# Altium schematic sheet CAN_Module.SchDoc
size 279 x 199 mm
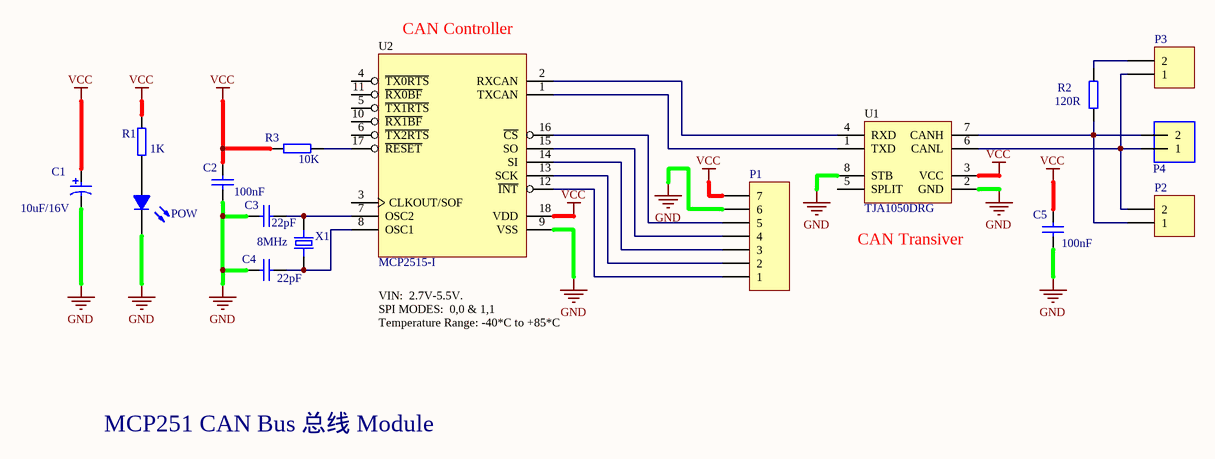
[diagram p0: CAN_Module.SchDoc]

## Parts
C1  10uF/16V  [tantalum  A]  (value not drawn)
C2  100nF  [C0603]  (value not drawn)
C3  22pF  [C0603]  (value not drawn)
C4  22pF  [C0603]  (value not drawn)
C5  100nF  [C0603]  (value not drawn)
P1  Header 7  [HDR1X7]  (value not drawn)
P2  Header 2  [HDR1X2]  (value not drawn)
P3  Header 2  [HDR1X2]  (value not drawn)
P4  Terminal Block 3.5mmPitch: 3,5 mmNumber of pins: 2Created by Rembrandt Electronicswww.rembrandtelectronics.com  [TERMINAL-BLOCK-2-PIN-3.5MM-ROUND-PAD]  (value not drawn)
POW  RED LED  [CHIPLED_0603]  (value not drawn)
R1  1kΩ  [R0603]  (value not drawn)
R2  120Ω  [R0603]  (value not drawn)
R3  10kΩ  [R0603]  (value not drawn)
U1  TJA1050DRG  [SOIC-8E]
U2  MCP2515-I  [SOIC-18_L11.6-W7.5-P1.27-LS10.3-BL]
X1  8MHz  [HC-49US_L11.5-W4.5-P4.88]  (value not drawn)

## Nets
GND: C1.2 C2.1 C3.2 C4.2 C5.1 P1.6 POW.C(K) U1.2(GND) U1.8(STB) U2.9(VSS)
VCC: C1.1 C2.2 C5.2 P1.7 R1.1 R3.2 U1.3(VCC) U2.18(VDD)
NetC3_1: C3.1 U2.7(OSC2) X1.2
NetC4_1: C4.1 U2.8(OSC1) X1.1
NetP1_1: P1.1 U2.12(~{INT})
NetP1_2: P1.2 U2.13(SCK)
NetP1_3: P1.3 U2.14(SI)
NetP1_4: P1.4 U2.15(SO)
NetP1_5: P1.5 U2.16(~{CS})
NetP2_1: P2.1 P4.2 R2.1 U1.7(CANH)
NetP2_2: P2.2 P3.1 P4.1 U1.6(CANL)
NetP3_2: P3.2 R2.2
NetPOW_A: POW.A R1.2
NetR3_1: R3.1 U2.17(~{RESET})
NetU1_1: U1.1(TXD) U2.1(TXCAN)
NetU1_4: U1.4(RXD) U2.2(RXCAN)

Not connected (* = marked no-connect by the designer): U1 5(SPLIT); U2 3(CLKOUT/SOF) 4(~{TX0RTS}) 5(~{TX1RTS}) 6(~{TX2RTS}) 10(~{RX1BF}) 11(~{RX0BF})

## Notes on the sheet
- (near U2) CAN Controller
- (near R2) 120R
- (near R1) 1K
- 100nF
- (near R3) 10K
- (near C1) 10uF/16V
- 8MHz
- (near C3) 22pF
- (near U1) CAN Transiver
- (near C5) 100nF
- (near C4) 22pF
- SPI MODES:  0,0 & 1,1
- Temperature Range: -40*C to +85*C
- VIN:  2.7V-5.5V.
- MCP251 CAN Bus 总线 Module

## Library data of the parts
C1 = Cap_Tantalum: SMD Tantalum Capacitor
C2-C5 = Cap_0603: Capacitor, X5R, ±10%, 6.3V; Part Number: C0603-N.C.; Manufacturer: N.A.; Artikkelnr Noca: 20069060
P1 = Header 7: Header, 7-Pin
P2 P3 = Header 2: Header, 2-Pin
P4 = TERMINAL-3.50-2P: Screw Terminal 3.5mm; SymbolName_1: TERMINAL-BLOCK-PIN-3.5MM; GateName_1: -1
POW = LEDCHIP-LED0603: SMD lamp beads
R1-R3 = Res_0603: Resistor, ±1%, 0.100W; Part Number: R0603-N.C.Ω; Manufacturer: N.A.; Note: Chip Res
U1 = TJA1050DRG: CAN Transiver; Manufacturer: HGC(深圳汉芯); Add into BOM: yes
U2 = MCP2515: CAN Controller; Manufacturer: Tokmas(托克马斯); Add into BOM: yes
X1 = CRYSTAL-ECS-100-20-5PVX: 10MHz Â±30ppm Crystal 20pF 60 Ohms HC-49/US; MF: ECS Inc.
